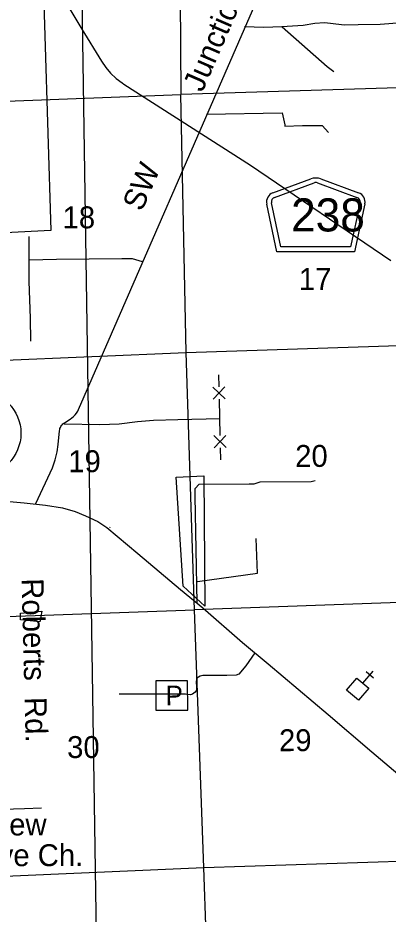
# Model space of a CAD drawing. Extents: x 2480962 to 2688785, y 277103 to 599240.
# Drawn here: x 2521274 to 2528890, y 340981 to 359405 of the extents above; entities that cross this region are included whole.
import ezdxf

# ---------------------------------------------------------------- set-up
doc = ezdxf.new("R2010")
doc.units = 0
for name, color, linetype in [('County Routes Highway Center Lines', 7, 'Continuous'), ('Culture', 7, 'Continuous'), ('Culture Text', 7, 'Continuous'), ('Divided_Highway', 7, 'Continuous'), ('Level 31', 7, 'Continuous'), ('Local Roads Improved', 7, 'Continuous'), ('Local Roads Paved', 7, 'Continuous'), ('Local Roads Related Cells', 7, 'Continuous'), ('Local Roads Related Text', 7, 'Continuous'), ('Local Roads Unimproved', 7, 'Continuous'), ('Planning Number US Highways', 7, 'Continuous'), ('Roadshields County Roads', 7, 'Continuous'), ('Section Lines', 7, 'Continuous'), ('Section Numbers', 7, 'Continuous'), ('State Park', 7, 'Continuous'), ('Uninventoried Roads and Features', 7, 'Continuous'), ('US Routes Highway Center Lines', 7, 'Continuous')]:
    doc.layers.add(name, color=color, linetype=linetype)

msp = doc.modelspace()

# ---------------------------------------------------------------- linework, layer by layer
at = {"layer": 'County Routes Highway Center Lines'}
for p, q in [((2521434.641, 361100.99), (2522586.904, 359172.624)), ((2522586.904, 359172.624), (2522992.388, 358512.545)), ((2523455.888, 358040.928), (2526057.855, 356379.666)), ((2526057.855, 356379.666), (2528945.378, 354417.365))]:
    msp.add_line(p, q, dxfattribs=at)
msp.add_lwpolyline([(2522992.388, 358512.545), (2523080.06, 358385.279), (2523180.554, 358267.874), (2523292.771, 358161.616), (2523415.48, 358067.671), (2523455.888, 358040.928)], dxfattribs=at)
at = {"layer": 'Culture'}
for p, q in [((2528371.014, 345728.57), (2528581.713, 345976.221)), ((2528440.651, 345964.743), (2528593.091, 345835.049))]:
    msp.add_line(p, q, dxfattribs=at)
msp.add_lwpolyline([(2528247.245, 345833.872), (2528494.784, 345623.269), (2528284.18, 345375.731), (2528036.643, 345586.334)], close=True, dxfattribs=at)
at = {"layer": 'Divided_Highway'}
msp.add_line((2523169.759, 322555.352), (2522471.387, 368007.737), dxfattribs=at)
at = {"layer": 'Level 31'}
for points in [[(2524530.029, 349961.912), (2525101.47, 349990.968), (2525120.841, 347308.1), (2524675.311, 347724.574)], [(2521764.488, 347208.318), (2521724.687, 346989.266), (2521326.677, 347029.093), (2521326.677, 347168.491)]]:
    msp.add_lwpolyline(points, close=True, dxfattribs=at)
at = {"layer": 'Local Roads Improved'}
for p, q in [((2522519.643, 351352.539), (2527698.559, 363225.495)), ((2522233.211, 351083.094), (2522347.983, 351154.255)), ((2522103.875, 350632.741), (2522130.542, 350917.355)), ((2521643.766, 349419.527), (2521986.077, 350157.132))]:
    msp.add_line(p, q, dxfattribs=at)
for points in [[(2522347.983, 351154.255), (2522385.849, 351180.572), (2522420.756, 351210.702), (2522452.323, 351244.318), (2522480.204, 351281.048), (2522504.092, 351320.491), (2522519.643, 351352.539)], [(2522130.542, 350917.355), (2522133.872, 350940.041), (2522139.556, 350962.253), (2522147.531, 350983.751), (2522157.708, 351004.296), (2522169.978, 351023.666), (2522184.205, 351041.647), (2522200.234, 351058.042), (2522217.889, 351072.672), (2522233.211, 351083.094)], [(2521986.077, 350157.132), (2522043.509, 350319.592), (2522083.646, 350487.166), (2522103.875, 350632.741)], [(2520505.085, 343121.878), (2521410.496, 343151.322), (2521756.465, 343166.045)]]:
    msp.add_lwpolyline(points, dxfattribs=at)
at = {"layer": 'Local Roads Paved'}
for points in [[(2525936.382, 359231.297), (2526333.905, 359217.835), (2526704.092, 359228.565), (2527144.025, 359255.39), (2527380.086, 359298.311), (2527583.958, 359309.041), (2527707.354, 359298.311), (2527986.335, 359260.755), (2528276.047, 359271.486), (2528726.71, 359276.851), (2529166.643, 359309.041), (2529461.72, 359309.041), (2529794.352, 359309.041), (2529966.033, 359292.946), (2529966.033, 359292.946)], [(2525156.054, 357424.784), (2526709.457, 357452.739), (2526763.107, 357205.947), (2526763.107, 357179.122), (2527127.93, 357189.852), (2527535.672, 357189.852), (2527664.433, 357050.361)], [(2521500.988, 354910.785), (2521500.988, 354425.599), (2521500.988, 353984.08), (2521525.247, 353232.042), (2521534.951, 352761.412)], [(2523834.731, 354391.636), (2523630.953, 354449.858), (2523412.62, 354449.858), (2522068.655, 354435.303), (2521505.839, 354425.599)]]:
    msp.add_lwpolyline(points, dxfattribs=at)
at = {"layer": 'Local Roads Related Cells'}
for p, q in [((2525403.859, 352069.297), (2525409.051, 351819.35)), ((2525539.216, 351572), (2525284.077, 351816.754)), ((2525534.024, 351821.946), (2525289.27, 351566.808)), ((2525414.243, 351569.404), (2525429.819, 350819.566)), ((2525559.985, 350572.216), (2525304.846, 350816.97)), ((2525554.792, 350822.162), (2525310.038, 350567.024)), ((2525435.011, 350569.62), (2525440.203, 350319.673))]:
    msp.add_line(p, q, dxfattribs=at)
at = {"layer": 'Local Roads Related Text'}
for p, q in [((2524763.276, 345778.116), (2524110.093, 345773.168)), ((2524110.093, 345773.168), (2524114.663, 345169.982)), ((2524767.846, 345174.93), (2524763.276, 345778.116)), ((2524114.663, 345169.982), (2524767.846, 345174.93))]:
    msp.add_line(p, q, dxfattribs=at)
at = {"layer": 'Local Roads Unimproved'}
for points in [[(2526710.491, 359220.319), (2527634.251, 358403.753), (2527771.7, 358300.883)], [(2522223.122, 351058.294), (2522956.909, 351044.046), (2523355.861, 351058.294), (2523733.441, 351108.163), (2524061.152, 351136.66), (2524566.966, 351150.908), (2525436.113, 351172.281)], [(2524958.795, 347382.234), (2524923.174, 349569.348), (2524923.174, 349733.203), (2525001.54, 349818.693), (2526034.541, 349825.817), (2526134.279, 349825.817), (2526255.39, 349868.562), (2527309.763, 349875.686), (2527388.129, 349897.058)], [(2524965.919, 347816.807), (2526205.52, 347987.787), (2526177.024, 348700.202)], [(2526148.185, 346353.481), (2525960.073, 346086.987), (2525818.988, 345914.551), (2525763.836, 345894.898), (2525570.459, 345885.973), (2525246.182, 345882.998), (2525079.581, 345885.973), (2525026.031, 345874.073), (2524954.63, 345832.423), (2524939.755, 345761.022), (2524945.705, 345636.071), (2524945.705, 345582.521), (2524921.905, 345543.846), (2524868.355, 345505.171), (2524823.729, 345487.32), (2524719.603, 345499.221), (2524674.978, 345499.221), (2523357.044, 345502.196)]]:
    msp.add_lwpolyline(points, dxfattribs=at)
at = {"layer": 'Planning Number US Highways'}
msp.add_circle((2520460.641, 350864.618), 875, dxfattribs=at)
at = {"layer": 'Roadshields County Roads'}
for p, q in [((2526520.094, 355808.459), (2527299.469, 356094.796)), ((2526554.58, 355714.594), (2527368.44, 356013.6)), ((2527437.411, 356013.6), (2528249.919, 355715.09)), ((2527506.382, 356094.796), (2528284.404, 355808.956)), ((2526684.9, 354696.634), (2526491.287, 355599.766)), ((2528313.212, 355600.263), (2528119.492, 354696.634)), ((2526604.066, 354596.633), (2526393.509, 355578.805)), ((2528410.99, 355579.302), (2528200.326, 354596.633)), ((2528119.492, 354696.633), (2526684.9, 354696.633)), ((2528200.326, 354596.633), (2526604.066, 354596.633))]:
    msp.add_line(p, q, dxfattribs=at)
for centre, radius, start, end in [((2527402.926, 355813.199), 300, 69.8269806, 110.1730139), ((2527402.925, 355919.735), 100, 69.8269876, 110.1729839), ((2526589.065, 355620.728), 200, 110.1729839, 192.0998896), ((2528215.433, 355621.225), 200, 347.9000917, 69.8270083), ((2526589.065, 355620.728), 100, 110.1729839, 192.0998896), ((2528215.433, 355621.224), 100, 347.9000932, 69.8269876)]:
    msp.add_arc(centre, radius, start, end, dxfattribs=at)
at = {"layer": 'Section Lines'}
for p, q in [((2524593.022, 363140.452), (2524624.479, 357827.747)), ((2530023.829, 357999.933), (2524624.479, 357827.747)), ((2519381.448, 357628.433), (2524624.479, 357827.747)), ((2524736.354, 352529.608), (2524624.479, 357827.747)), ((2524625.15, 357797.07), (2524624.48, 357827.747)), ((2524736.354, 352529.608), (2530126.711, 352704.228)), ((2519497.455, 352299.896), (2524736.354, 352529.608)), ((2524910.296, 347232.253), (2524736.353, 352529.608)), ((2535556.41, 347623.885), (2524910.177, 347235.537)), ((2524910.296, 347232.253), (2519655, 347037.313)), ((2525100.227, 341937.109), (2524910.177, 347235.537)), ((2525100.227, 341937.109), (2530402.681, 342113.03)), ((2519817.177, 341711.177), (2525100.227, 341937.109)), ((2525274.359, 336625.682), (2525100.227, 341937.109))]:
    msp.add_line(p, q, dxfattribs=at)
at = {"layer": 'State Park'}
msp.add_lwpolyline([(2521704.552, 363048.415), (2521951.039, 355032.033), (2520472.118, 354958.035)], dxfattribs=at)
at = {"layer": 'Uninventoried Roads and Features'}
msp.add_lwpolyline([(2523162.806, 348936.975), (2523161.673, 348923.226)], dxfattribs=at)
at = {"layer": 'US Routes Highway Center Lines'}
msp.add_lwpolyline([(2519408.214, 349611.41), (2521401.175, 349432.829), (2521844.055, 349389.97), (2522194.073, 349332.824), (2522451.229, 349254.249), (2522665.526, 349168.53), (2522915.539, 349054.238), (2523101.263, 348925.66), (2523744.153, 348397.061), (2524615.627, 347654.166), (2525079.937, 347275.575), (2525894.265, 346561.252), (2526422.864, 346125.515), (2527658.642, 345082.604), (2528558.689, 344318.278), (2529623.03, 343411.088)], dxfattribs=at)

# ---------------------------------------------------------------- texts
at = {"layer": 'Culture Text'}
for s, p in [('New', (2520660.694, 342597.025)), ('Grove Ch.', (2519876.234, 341963.919))]:
    msp.add_text(s, height=450, rotation=0.0672139, dxfattribs=at).set_placement(p)
at = {"layer": 'Local Roads Related Text'}
for s, height, rotation, p in [('Junction    Rd.', 450, 66.58545, (2525068.739, 357859.044)), ('SW', 450, 66.5854306, (2523822.827, 355407.055)), ('Roberts  Rd.', 450, 271.4649472, (2521349.057, 347878.694)), ('P', 400, 0.4340506, (2524313.282, 345274.745))]:
    msp.add_text(s, height=height, rotation=rotation, dxfattribs=at).set_placement(p)
at = {"layer": 'Roadshields County Roads'}
msp.add_text('238', height=680, dxfattribs=at).set_placement((2526894.68, 355014.918))
at = {"layer": 'Section Numbers'}
for s, rotation, p in [('18', 0.0672111, (2522193.511, 355079.277)), ('17', 0.0672472, (2527054.143, 353811.778)), ('20', 0.0672361, (2526978.709, 350174.286)), ('19', 0.067225, (2522310.473, 350065.176)), ('29', 0.0672222, (2526646.178, 344329.769)), ('30', 0.0672111, (2522286.473, 344188.961))]:
    msp.add_text(s, height=450, rotation=rotation, dxfattribs=at).set_placement(p)

doc.saveas('drawing.dxf')
